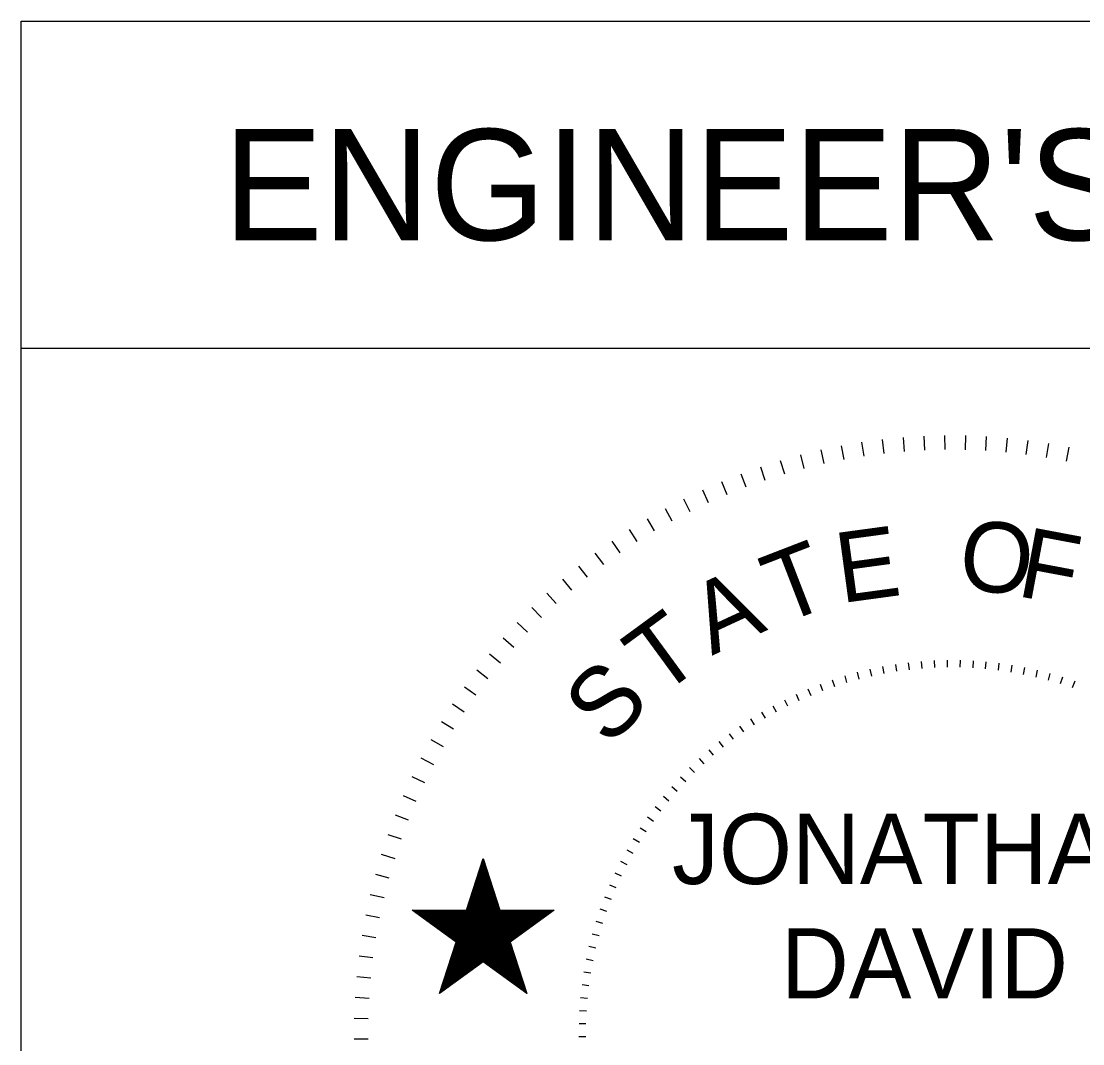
# Model space of a CAD drawing. Extents: x -10 to 89.7, y -4.8 to 22.
# Drawn here: x 8.45 to 10.073, y -3.15 to -1.586 of the extents above; entities that cross this region are included whole.
import ezdxf

# ---------------------------------------------------------------- set-up
doc = ezdxf.new("R2010")
doc.units = 0
doc.layers.add('GM_X_Minor_Lake', color=7, linetype='Continuous')
doc.layers.add('GM_X_Minor_River_Text', color=7, linetype='Continuous')

msp = doc.modelspace()

# ---------------------------------------------------------------- linework, layer by layer
at = {"layer": 'GM_X_Minor_Lake'}
for p, q in [((8.45, -4.8358), (8.45, -1.5858)), ((8.45, -1.5858), (11.25, -1.5858)), ((8.45, -2.0858), (11.25, -2.0858)), ((9.7986, -2.2225), (9.8003, -2.2439)), ((9.8303, -2.2204), (9.8313, -2.2419)), ((9.8622, -2.2195), (9.8624, -2.241)), ((9.8941, -2.2197), (9.8936, -2.2412)), ((9.9259, -2.221), (9.9247, -2.2425)), ((9.9577, -2.2235), (9.9557, -2.2449)), ((9.7038, -2.2351), (9.7078, -2.2562)), ((9.7352, -2.2297), (9.7384, -2.251)), ((9.7668, -2.2256), (9.7693, -2.2469)), ((9.9893, -2.227), (9.9866, -2.2484)), ((10.0209, -2.2316), (10.0174, -2.2529)), ((10.0522, -2.2374), (10.0481, -2.2585)), ((9.6416, -2.2491), (9.6471, -2.2699)), ((9.6726, -2.2415), (9.6773, -2.2625)), ((9.5806, -2.2672), (9.5874, -2.2876)), ((9.6109, -2.2576), (9.6171, -2.2782)), ((9.5506, -2.278), (9.5581, -2.2981)), ((9.4917, -2.3025), (9.5007, -2.322)), ((9.5209, -2.2897), (9.5292, -2.3096)), ((9.4629, -2.3162), (9.4726, -2.3355)), ((9.4347, -2.3311), (9.4451, -2.35)), ((9.4071, -2.3469), (9.4179, -2.3654)), ((9.3799, -2.3635), (9.3914, -2.3816)), ((9.3533, -2.3812), (9.3656, -2.3989)), ((9.3274, -2.3997), (9.3403, -2.417)), ((9.3022, -2.4192), (9.3156, -2.436)), ((9.2777, -2.4395), (9.2917, -2.4559)), ((9.2538, -2.4607), (9.2683, -2.4765)), ((9.2307, -2.4827), (9.2458, -2.498)), ((9.2084, -2.5055), (9.2241, -2.5202)), ((9.1869, -2.529), (9.2031, -2.5432)), ((9.1663, -2.5534), (9.1829, -2.567)), ((9.8461, -2.5639), (9.8466, -2.5745)), ((9.8659, -2.5632), (9.8661, -2.574)), ((9.8858, -2.5634), (9.8856, -2.5741)), ((9.9057, -2.5642), (9.9051, -2.5749)), ((9.1466, -2.5782), (9.1636, -2.5914)), ((9.7477, -2.577), (9.7501, -2.5875)), ((9.7672, -2.573), (9.7692, -2.5835)), ((9.7868, -2.5696), (9.7884, -2.5802)), ((9.8064, -2.567), (9.8077, -2.5777)), ((9.8263, -2.5651), (9.8271, -2.5757)), ((9.9254, -2.5657), (9.9244, -2.5764)), ((9.9452, -2.5679), (9.9438, -2.5786)), ((9.9649, -2.5709), (9.9632, -2.5814)), ((9.9844, -2.5744), (9.9823, -2.5849)), ((10.0038, -2.5786), (10.0014, -2.5891)), ((9.6903, -2.593), (9.6938, -2.6032)), ((9.7093, -2.587), (9.7123, -2.5974)), ((9.7284, -2.5816), (9.7311, -2.5921)), ((10.0231, -2.5836), (10.0203, -2.594)), ((10.0422, -2.5892), (10.0389, -2.5995)), ((10.0611, -2.5955), (10.0574, -2.6056)), ((9.1277, -2.604), (9.1452, -2.6164)), ((9.6532, -2.607), (9.6573, -2.617)), ((9.6716, -2.5997), (9.6754, -2.6097)), ((9.6171, -2.6236), (9.6218, -2.6332)), ((9.6349, -2.615), (9.6394, -2.6247)), ((9.1097, -2.6302), (9.1276, -2.6421)), ((9.5822, -2.6426), (9.5876, -2.6519)), ((9.5994, -2.6329), (9.6046, -2.6422)), ((9.0926, -2.6572), (9.1109, -2.6684)), ((9.5652, -2.6531), (9.5711, -2.6621)), ((9.5326, -2.6756), (9.5389, -2.6842)), ((9.5487, -2.6641), (9.5548, -2.6729)), ((9.0764, -2.6847), (9.0952, -2.6952)), ((9.5168, -2.6877), (9.5234, -2.6961)), ((9.5014, -2.7005), (9.5084, -2.7086)), ((9.0613, -2.7127), (9.0804, -2.7226)), ((9.4866, -2.7136), (9.4939, -2.7215)), ((9.0472, -2.7412), (9.0666, -2.7505)), ((9.4583, -2.7416), (9.4662, -2.749)), ((9.4722, -2.7274), (9.4798, -2.735)), ((9.4449, -2.7562), (9.4529, -2.7634)), ((9.0341, -2.7704), (9.0537, -2.7789)), ((9.4321, -2.7714), (9.4403, -2.7782)), ((9.4197, -2.787), (9.4283, -2.7935)), ((9.0219, -2.7997), (9.0419, -2.8076)), ((9.4079, -2.803), (9.4167, -2.8092)), ((9.3967, -2.8194), (9.4057, -2.8252)), ((9.0108, -2.8296), (9.0311, -2.8367)), ((9.3861, -2.8361), (9.3953, -2.8417)), ((9.3761, -2.8532), (9.3854, -2.8586)), ((9.0007, -2.8599), (9.0213, -2.8664)), ((9.1309, -2.9455), (9.1563, -2.8666)), ((9.1521, -2.8799), (9.1584, -2.8734)), ((9.1529, -2.877), (9.1581, -2.872)), ((9.1538, -2.8742), (9.1576, -2.8705)), ((9.1547, -2.8715), (9.1571, -2.8691)), ((9.1557, -2.8686), (9.1566, -2.8676)), ((9.1563, -2.8666), (9.1819, -2.9455)), ((9.3666, -2.8707), (9.3762, -2.8757)), ((9.1421, -2.9106), (9.1636, -2.8891)), ((9.1429, -2.9079), (9.1632, -2.8876)), ((9.1439, -2.905), (9.1627, -2.8862)), ((9.1448, -2.9021), (9.1622, -2.8849)), ((9.1458, -2.8994), (9.1618, -2.8834)), ((9.1467, -2.8966), (9.1612, -2.882)), ((9.1474, -2.8937), (9.1608, -2.8806)), ((9.1484, -2.891), (9.1604, -2.8791)), ((9.1493, -2.8882), (9.1598, -2.8776)), ((9.1503, -2.8854), (9.1594, -2.8762)), ((9.1512, -2.8826), (9.1589, -2.8747)), ((9.3578, -2.8886), (9.3674, -2.8932)), ((8.9918, -2.8905), (9.0124, -2.8962)), ((9.1322, -2.9414), (9.1688, -2.9049)), ((9.1331, -2.9386), (9.1682, -2.9035)), ((9.1341, -2.9357), (9.1678, -2.902)), ((9.1349, -2.933), (9.1673, -2.9005)), ((9.1358, -2.9302), (9.1668, -2.8991)), ((9.1367, -2.9274), (9.1664, -2.8977)), ((9.1376, -2.9246), (9.1659, -2.8962)), ((9.1384, -2.9219), (9.1654, -2.8949)), ((9.1394, -2.919), (9.1649, -2.8935)), ((9.1403, -2.9162), (9.1646, -2.892)), ((9.1413, -2.9135), (9.1641, -2.8905)), ((8.9838, -2.9214), (9.0048, -2.9264)), ((9.0964, -2.981), (9.1696, -2.9077)), ((9.0976, -2.9817), (9.1702, -2.9091)), ((9.0986, -2.9826), (9.1706, -2.9106)), ((9.0997, -2.9834), (9.1711, -2.912)), ((9.1008, -2.9841), (9.1716, -2.9135)), ((9.1019, -2.985), (9.1719, -2.915)), ((9.1031, -2.9857), (9.1724, -2.9164)), ((9.1041, -2.9866), (9.1729, -2.9177)), ((9.1053, -2.9874), (9.1734, -2.9192)), ((9.1063, -2.9882), (9.1738, -2.9206)), ((9.1074, -2.989), (9.1743, -2.9221)), ((9.1313, -2.9441), (9.1692, -2.9064)), ((9.3496, -2.9067), (9.3594, -2.911)), ((9.1084, -2.9897), (9.1748, -2.9235)), ((9.1097, -2.9906), (9.1752, -2.9249)), ((9.1108, -2.9914), (9.1757, -2.9265)), ((9.1116, -3.0059), (9.1794, -2.9379)), ((9.1118, -2.9921), (9.1762, -2.9279)), ((9.1123, -3.003), (9.1789, -2.9364)), ((9.1129, -2.9929), (9.1766, -2.9292)), ((9.1133, -3.0002), (9.1786, -2.935)), ((9.1141, -2.9937), (9.1772, -2.9307)), ((9.1142, -2.9975), (9.1779, -2.9335)), ((9.1151, -2.9946), (9.1776, -2.9321)), ((9.3419, -2.9251), (9.3521, -2.929)), ((8.9771, -2.9525), (8.9981, -2.9567)), ((9.1151, -2.9945), (9.0477, -2.9455)), ((9.0477, -2.9455), (9.1309, -2.9455)), ((9.0481, -2.9457), (9.0483, -2.9455)), ((9.0491, -2.9466), (9.0503, -2.9455)), ((9.0503, -2.9474), (9.0521, -2.9455)), ((9.0513, -2.9482), (9.0541, -2.9455)), ((9.0524, -2.949), (9.0559, -2.9455)), ((9.0534, -2.9499), (9.0578, -2.9455)), ((9.0547, -2.9506), (9.0597, -2.9455)), ((9.0558, -2.9514), (9.0617, -2.9455)), ((9.0568, -2.9522), (9.0634, -2.9455)), ((9.0579, -2.953), (9.0654, -2.9455)), ((9.0591, -2.9539), (9.0673, -2.9455)), ((9.0602, -2.9546), (9.0692, -2.9455)), ((9.0612, -2.9555), (9.0711, -2.9455)), ((9.0623, -2.9562), (9.0731, -2.9455)), ((9.0634, -2.957), (9.0748, -2.9455)), ((9.0646, -2.9577), (9.0768, -2.9455)), ((9.0657, -2.9585), (9.0787, -2.9455)), ((9.0667, -2.9594), (9.0806, -2.9455)), ((9.0679, -2.9601), (9.0824, -2.9455)), ((9.0689, -2.961), (9.0844, -2.9455)), ((9.0701, -2.9617), (9.0863, -2.9455)), ((9.0711, -2.9626), (9.0882, -2.9455)), ((9.0723, -2.9634), (9.0902, -2.9455)), ((9.0733, -2.9641), (9.0921, -2.9455)), ((9.0744, -2.965), (9.0939, -2.9455)), ((9.0756, -2.9657), (9.0958, -2.9455)), ((9.0766, -2.9666), (9.0978, -2.9455)), ((9.0778, -2.9674), (9.0996, -2.9455)), ((9.0788, -2.9682), (9.1016, -2.9455)), ((9.0799, -2.969), (9.1034, -2.9455)), ((9.0809, -2.9699), (9.1053, -2.9455)), ((9.0822, -2.9706), (9.1072, -2.9455)), ((9.0833, -2.9714), (9.1092, -2.9455)), ((9.0843, -2.9722), (9.1109, -2.9455)), ((9.0854, -2.973), (9.1129, -2.9455)), ((9.0866, -2.9739), (9.1148, -2.9455)), ((9.0877, -2.9746), (9.1167, -2.9455)), ((9.0887, -2.9754), (9.1186, -2.9455)), ((9.0898, -2.9761), (9.1206, -2.9455)), ((9.0898, -3.073), (9.2173, -2.9455)), ((9.0908, -3.0701), (9.2154, -2.9455)), ((9.0909, -2.9769), (9.1223, -2.9455)), ((9.0917, -3.0674), (9.2136, -2.9455)), ((9.0921, -2.9777), (9.1243, -2.9455)), ((9.0926, -3.0646), (9.2116, -2.9455)), ((9.0932, -2.9785), (9.1262, -2.9455)), ((9.0934, -3.0617), (9.2098, -2.9455)), ((9.0942, -2.9794), (9.1281, -2.9455)), ((9.0943, -3.059), (9.2078, -2.9455)), ((9.0953, -3.0562), (9.2059, -2.9455)), ((9.0954, -2.9801), (9.1299, -2.9455)), ((9.0962, -3.0534), (9.2039, -2.9455)), ((9.0962, -3.0685), (9.2192, -2.9455)), ((9.0971, -3.0506), (9.2022, -2.9455)), ((9.0979, -3.0479), (9.2002, -2.9455)), ((9.0988, -3.045), (9.1983, -2.9455)), ((9.0998, -3.0422), (9.1964, -2.9455)), ((9.1007, -3.0395), (9.1946, -2.9455)), ((9.1016, -3.0366), (9.1926, -2.9455)), ((9.1024, -3.0339), (9.1908, -2.9455)), ((9.1032, -3.0634), (9.2212, -2.9455)), ((9.1033, -3.031), (9.1888, -2.9455)), ((9.1043, -3.0281), (9.1869, -2.9455)), ((9.1052, -3.0254), (9.1851, -2.9455)), ((9.1061, -3.0226), (9.1832, -2.9455)), ((9.1069, -3.0197), (9.1818, -2.945)), ((9.1078, -3.017), (9.1813, -2.9436)), ((9.1088, -3.0142), (9.1808, -2.9421)), ((9.1097, -3.0114), (9.1803, -2.9407)), ((9.1103, -3.0582), (9.2231, -2.9455)), ((9.1106, -3.0086), (9.1799, -2.9394)), ((9.1173, -3.0532), (9.2249, -2.9455)), ((9.1243, -3.048), (9.2268, -2.9455)), ((9.1313, -3.043), (9.2287, -2.9455)), ((9.1383, -3.0379), (9.2307, -2.9455)), ((9.1453, -3.0326), (9.2326, -2.9455)), ((9.1523, -3.0276), (9.2344, -2.9455)), ((9.1569, -3.025), (9.2363, -2.9455)), ((9.1581, -3.0257), (9.2383, -2.9455)), ((9.1591, -3.0265), (9.2401, -2.9455)), ((9.1603, -3.0272), (9.2421, -2.9455)), ((9.1613, -3.0281), (9.2439, -2.9455)), ((9.1624, -3.0289), (9.2458, -2.9455)), ((9.1819, -2.9455), (9.2649, -2.9455)), ((9.2649, -2.9455), (9.1978, -2.9945)), ((9.2014, -2.9919), (9.2477, -2.9455)), ((9.2084, -2.9867), (9.2497, -2.9455)), ((9.2154, -2.9815), (9.2514, -2.9455)), ((9.2224, -2.9765), (9.2534, -2.9455)), ((9.2294, -2.9714), (9.2553, -2.9455)), ((9.2366, -2.9662), (9.2572, -2.9455)), ((9.2436, -2.9611), (9.2591, -2.9455)), ((9.2506, -2.956), (9.2611, -2.9455)), ((9.2574, -2.9509), (9.2629, -2.9455)), ((9.2646, -2.9457), (9.2648, -2.9455)), ((9.3351, -2.9437), (9.3452, -2.9472)), ((9.3288, -2.9625), (9.3391, -2.9657)), ((8.9713, -2.9839), (8.9924, -2.9874)), ((9.3232, -2.9816), (9.3336, -2.9845)), ((9.0898, -3.0732), (9.1151, -2.9945)), ((9.1634, -3.0296), (9.1981, -2.9952)), ((9.1647, -3.0305), (9.1986, -2.9966)), ((9.1658, -3.0312), (9.1989, -2.9981)), ((9.1668, -3.0321), (9.1994, -2.9995)), ((9.1679, -3.0329), (9.1999, -3.0009)), ((9.1691, -3.0337), (9.2003, -3.0024)), ((9.1978, -2.9945), (9.2234, -3.0732)), ((9.3183, -3.0009), (9.3287, -3.0034)), ((8.9667, -3.0154), (8.9879, -3.0181)), ((9.1702, -3.0345), (9.2009, -3.0037)), ((9.1712, -3.0354), (9.2013, -3.0051)), ((9.1723, -3.0361), (9.2017, -3.0066)), ((9.1734, -3.0369), (9.2023, -3.0081)), ((9.1746, -3.0377), (9.2027, -3.0095)), ((9.1757, -3.0385), (9.2032, -3.011)), ((9.1767, -3.0394), (9.2037, -3.0124)), ((9.1778, -3.0401), (9.2041, -3.0137)), ((9.1789, -3.041), (9.2046, -3.0152)), ((9.1801, -3.0417), (9.2051, -3.0166)), ((9.1811, -3.0425), (9.2054, -3.0181)), ((9.1564, -3.0246), (9.0898, -3.0732)), ((9.2234, -3.0732), (9.1564, -3.0246)), ((9.1822, -3.0434), (9.2059, -3.0196)), ((9.1833, -3.0441), (9.2064, -3.021)), ((9.1844, -3.0449), (9.2069, -3.0224)), ((9.1856, -3.0456), (9.2073, -3.0239)), ((9.1866, -3.0465), (9.2078, -3.0252)), ((9.1878, -3.0472), (9.2083, -3.0267)), ((9.1888, -3.0481), (9.2087, -3.0281)), ((9.1899, -3.0489), (9.2093, -3.0296)), ((9.1909, -3.0496), (9.2097, -3.0311)), ((9.1922, -3.0505), (9.2102, -3.0325)), ((9.1933, -3.0512), (9.2107, -3.0339)), ((9.1943, -3.0521), (9.2111, -3.0354)), ((9.3141, -3.0202), (9.3246, -3.0224)), ((8.9631, -3.047), (8.9844, -3.0491)), ((9.1954, -3.0529), (9.2116, -3.0367)), ((9.1964, -3.0537), (9.2121, -3.0381)), ((9.1977, -3.0545), (9.2124, -3.0396)), ((9.1987, -3.0552), (9.2131, -3.041)), ((9.1998, -3.0561), (9.2134, -3.0425)), ((9.2009, -3.0569), (9.2139, -3.044)), ((9.2021, -3.0577), (9.2144, -3.0454)), ((9.2032, -3.0585), (9.2148, -3.0467)), ((9.2042, -3.0594), (9.2153, -3.0482)), ((9.2053, -3.0601), (9.2158, -3.0496)), ((9.2064, -3.0609), (9.2162, -3.051)), ((9.3104, -3.0399), (9.3211, -3.0416)), ((9.2076, -3.0616), (9.2167, -3.0525)), ((9.2086, -3.0624), (9.2172, -3.054)), ((9.2097, -3.0632), (9.2177, -3.0554)), ((9.2108, -3.064), (9.2181, -3.0569)), ((9.2119, -3.0649), (9.2186, -3.0582)), ((9.2131, -3.0656), (9.2191, -3.0596)), ((9.2141, -3.0665), (9.2194, -3.0611)), ((9.2153, -3.0672), (9.2199, -3.0625)), ((9.2163, -3.068), (9.2204, -3.064)), ((9.2174, -3.0689), (9.2208, -3.0655)), ((9.2184, -3.0696), (9.2214, -3.0669)), ((9.2197, -3.0705), (9.2218, -3.0682)), ((9.3076, -3.0595), (9.3182, -3.0609)), ((8.9607, -3.0789), (8.9821, -3.0801)), ((9.2208, -3.0712), (9.2223, -3.0697)), ((9.2218, -3.0721), (9.2228, -3.0711)), ((9.2229, -3.0729), (9.2232, -3.0725)), ((9.3053, -3.0792), (9.3161, -3.0802)), ((9.3038, -3.099), (9.3146, -3.0997)), ((8.9593, -3.1106), (8.9808, -3.1112)), ((9.3031, -3.1189), (9.3137, -3.1191)), ((8.9592, -3.1425), (8.9807, -3.1422)), ((9.3029, -3.1387), (9.3136, -3.1386))]:
    msp.add_line(p, q, dxfattribs=at)

# ---------------------------------------------------------------- texts
for s, rotation, p in [('O', 353.6025, (9.8807, -2.4531)), ('E', 7.7343, (9.7036, -2.4761)), ('F', 349.3508, (9.9706, -2.4646)), ('T', 21.1398, (9.6118, -2.5094)), ('A', 24.8261, (9.5062, -2.5565)), ('T', 36.224, (9.4262, -2.6205)), ('S', 45.0535, (9.3478, -2.6975))]:
    msp.add_text(s, height=0.1074, rotation=rotation, dxfattribs=at).set_placement(p)
for s, p in [('JONATHAN', (9.4453, -2.9056)), ('DAVID', (9.6119, -3.0806))]:
    msp.add_text(s, height=0.10742, dxfattribs=at).set_placement(p)
at = {"layer": 'GM_X_Minor_River_Text'}
msp.add_text("ENGINEER'S SEAL:", height=0.17, dxfattribs=at).set_placement((8.7595, -1.9208))

doc.saveas('drawing.dxf')
